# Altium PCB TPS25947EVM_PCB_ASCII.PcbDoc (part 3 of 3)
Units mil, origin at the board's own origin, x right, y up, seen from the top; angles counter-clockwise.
Board outline 6500 x 3000 mil, 4 copper layers (L1-Top Layer, L2-GND1, L3-PWR/SIG, L4-Bottom Layer), stack 63.4 mil thick; 232 components, 92 nets, 448 pads, 577 vias.
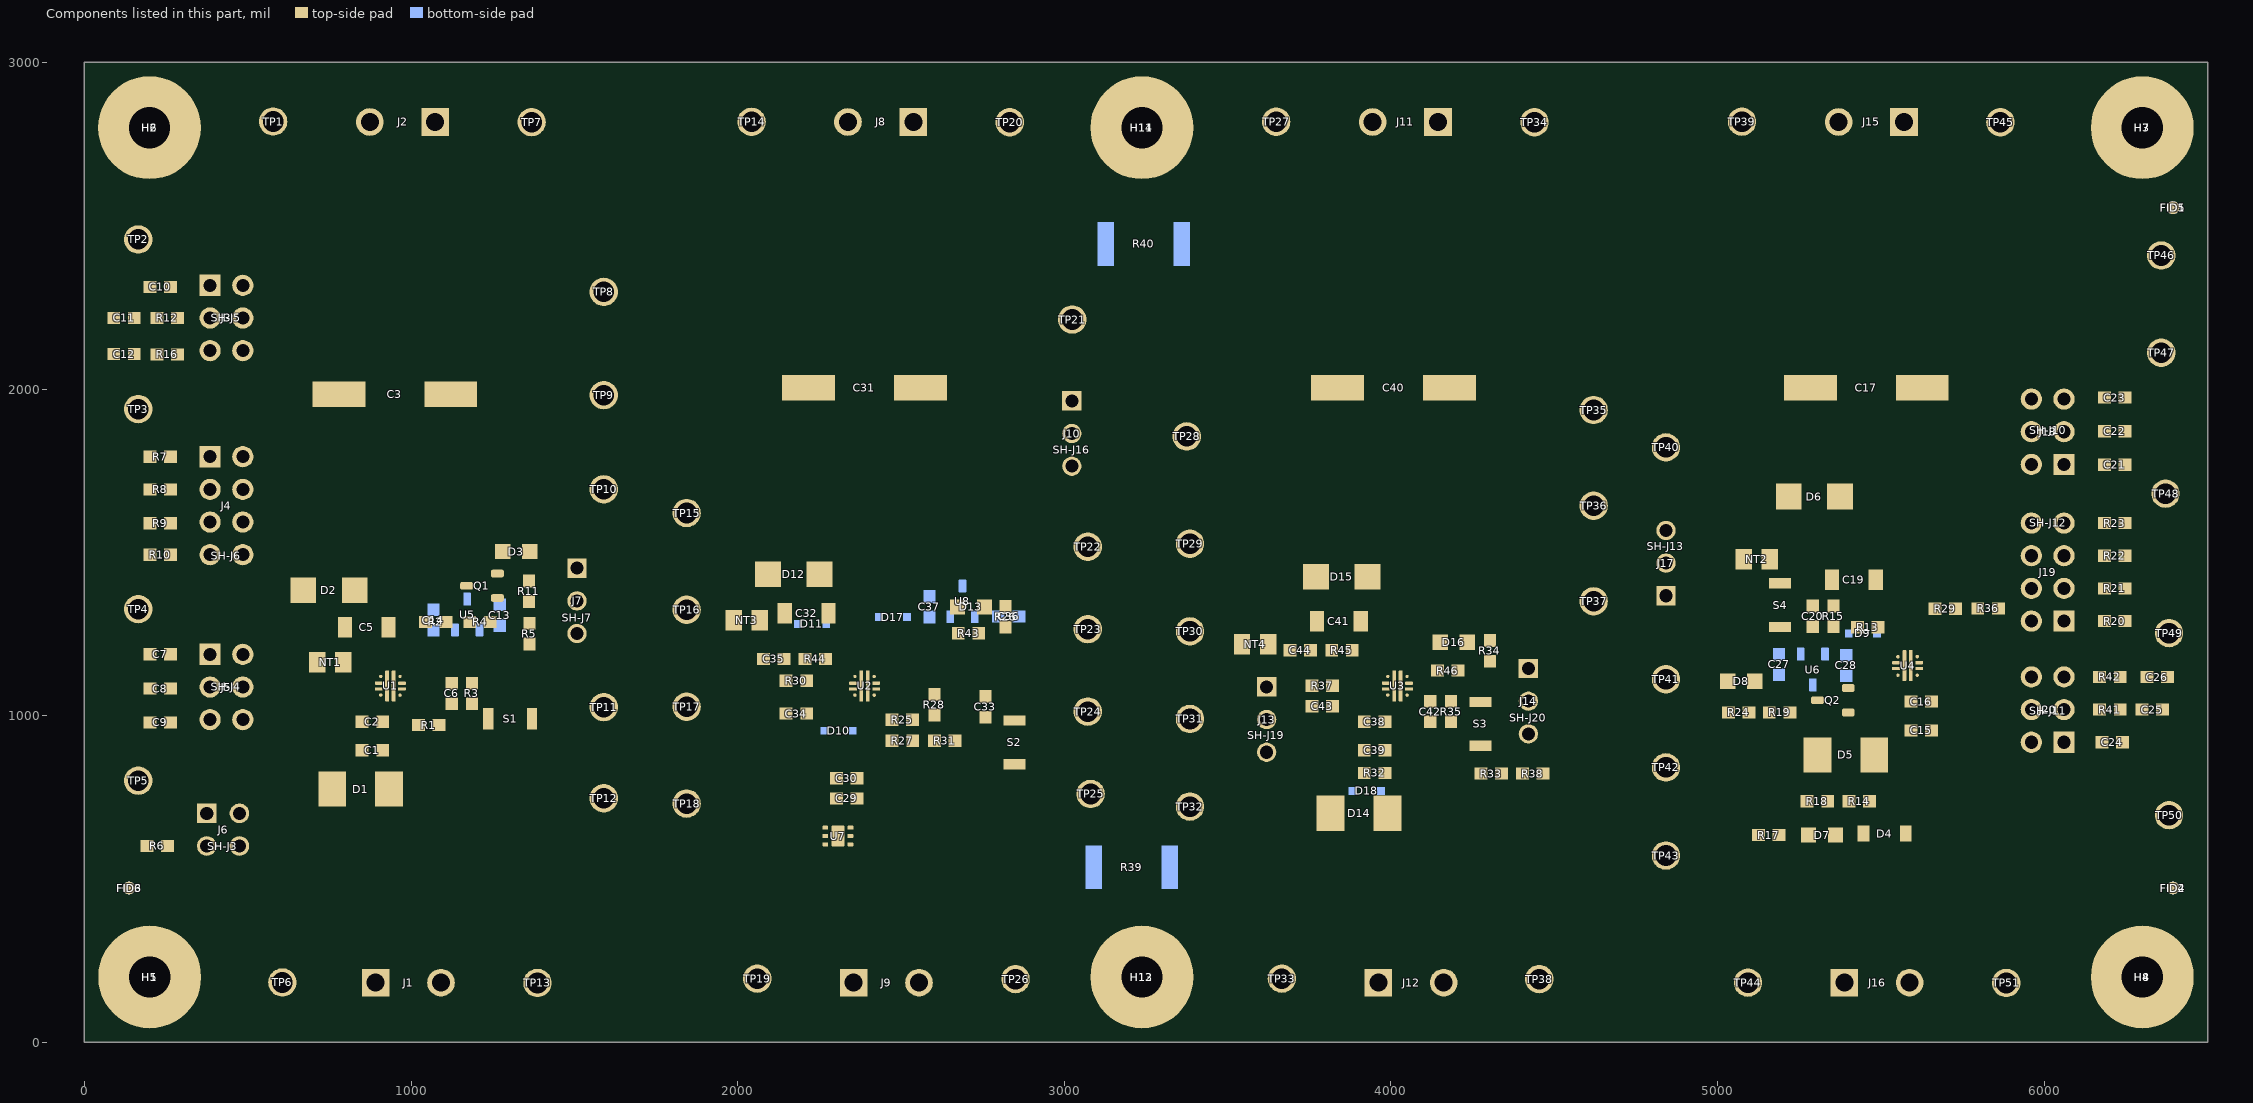
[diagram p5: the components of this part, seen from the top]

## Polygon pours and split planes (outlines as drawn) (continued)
PGND4 on L1-Top Layer "L1-TOP_LAYER_PGND4_P198" (solid, remove dead copper, pour order 198): 5241.83,585.7 5217.29,610.24 5217.29,780.84 5242.85,806.4 5401.8,806.4 5413.77,818.37 5413.77,951.12 5406.54,958.35 5079.85,958.35 5054.9,983.3 5054.9,1309.99 5115.6,1370.69 5115.6,1539.62 5175.32,1599.34 5274.23,1599.34 5292,1617.11 5292,1716.02 5292,1848.56 5456.1,2012.66 5456.1,2872.6 5456.1,2921.2 5419.82,2957.48 4753.68,2957.48 4713.77,2917.57 4713.78,65.62 4739.17,40.23 5440.2,40.23 5477.17,75.84 5477.17,229.99 5477.17,448.39 5477.17,558.13 5449.6,585.7
PGND on L1-Top Layer "L1-TOP_LAYER_PGND_P136" (solid, remove dead copper, pour order 136): 4033.53,262.43 4033.53,277.8 3922.85,388.48 3922.85,727.56 3815.8,834.61 3586.66,834.61 3569.32,851.95 3569.32,1302.32 3636.74,1369.74 3865.56,1369.74 3870.51,1374.69 3870.51,1603.51 3870.51,1853.94 4005.5,1988.93 4005.5,2927.18 3987.68,2945 3290.46,2945 3249.09,2903.63 3249.09,97.1 3306.48,39.7 4004.66,39.7 4033.53,68.56 4033.53,195.15
VIN3 on L1-Top Layer "L1-TOP_LAYER_VIN3_P160" (solid, remove dead copper, pour order 160): 4307.03,797.97 4320.01,784.99 4683.34,784.99 4695.4,772.93 4695.4,287.52 4695.4,64.6 4671.03,40.23 4085.26,40.23 4066.97,58.52 4052.34,73.15 4052.34,282.71 3949.81,385.24 3949.81,804.96 3949.81,1010.2 3961.27,1021.66 4001.85,1021.66 4029.57,1049.38 4076.12,1002.83 4076.12,966.08 4179.54,862.66 4280.71,862.66 4307.03,836.34
VOUT3 on L1-Top Layer "L1-TOP_LAYER_VOUT3_P168" (solid, remove dead copper, pour order 168): 4114,1282.7 4678.65,1282.7 4695.4,1299.46 4695.4,2234.3 4695.4,2915.3 4665.7,2945 4035.36,2945 4020.79,2930.44 4020.79,2736.18 4020.79,1976.24 3885.8,1841.25 3885.8,1258.09 4011.83,1132.06 4108.98,1229.21 4108.98,1277.68
PGND1 on L1-Top Layer "L1-TOP_LAYER_PGND1_P100" (solid, remove dead copper, pour order 100): 978.2,53.6 964.3,39.7 408.7,39.7 380.95,67.45 380.95,470.16 432.76,521.98 520.38,521.98 557.2,558.79 557.2,2416 394.18,2579.02 394.18,2931.41 420.25,2957.48 932.92,2957.48 959.37,2931.03 959.37,1994.84 754.1,1789.57 754.1,870.87 790.61,834.36 855.08,834.36 872.38,817.06 872.38,376.57 978.2,270.74
PGND1 on L1-Top Layer "L1-TOP_LAYER_PGND1_P098" (solid, remove dead copper, pour order 98): 1231.53,1454.75 1225.62,1448.85 1225.62,1393.24 1229.74,1388.22 1315.32,1388.22 1325.75,1398.65 1325.75,1444.66 1315.66,1454.75
VOUT4 on L1-Top Layer "L1-TOP_LAYER_VOUT4_P206" (solid, remove dead copper, pour order 206): 5930.76,2039.26 6452.66,2039.26 6457.48,2044.08 6457.48,2891.89 6391.58,2957.79 6390.29,2956.5 5973.23,2956.5 5503.3,2956.5 5469.69,2922.89 5469.56,1998.48 5311.32,1840.24 5311.32,1588.78 5425.7,1474.4 5425.7,1404.06 5462.67,1367.1 5528.38,1367.1 5585.41,1310.07 5585.41,1193.04 5591.37,1187.07 5597.22,1192.92 5597.22,1198.53 5598.04,1198.53 5614.75,1215.24 5628.65,1215.24 5683.2,1269.8 5683.2,1791.7
VIN4 on L1-Top Layer "L1-TOP_LAYER_VIN4_P200" (solid, remove dead copper, pour order 200): 5495.1,669.31 5430.33,734.08 5430.33,969.73 5566.59,1105.99 5577.11,1105.99 5616.6,1066.5 5616.6,914.4 5843.31,687.69 6084.3,446.7 6084.3,77.38 6046.71,39.78 5535.52,39.78 5495.1,80.2
VIN4 on L1-Top Layer "L1-TOP_LAYER_VIN4_P204" (solid, remove dead copper, pour order 204): 5545.33,1226.29 5494.71,1226.29 5471.21,1249.79 5471.21,1337.1 5481.51,1347.4 5524.5,1347.4 5578.3,1293.6 5578.3,1200.5 5576.33,1198.53 5565.72,1198.53 5565.72,1205.9
EN/UVLO4 on L1-Top Layer "L1-Top Layer-EN/UVLO4" (solid, remove dead copper, pour order 202): 5498,1205.9 5551.06,1205.9 5556.64,1200.33 5556.64,1180.17 5551.94,1175.48 5457.69,1175.48 5457.1,1174.89 5396.56,1235.43 5130.88,1235.43 5123.68,1242.63 5123.68,1282.62 5134.03,1292.97 5444.53,1292.97 5452,1285.5 5452,1251.9
VCC on L1-Top Layer "L1-Top Layer-VCC" (solid, remove dead copper, pour order 124): 4321.73,1186.39 4327.4,1180.72 4327.4,1109.92 4320.01,1102.53 4194.91,1102.53 4183.45,1113.98 4183.45,1175.56 4194.28,1186.39
EN/UVLO3 on L1-Top Layer "L1-TOP_LAYER_EN/UVLO3_P162" (solid, remove dead copper, pour order 162): 4212.28,1024.61 4242.87,994.02 4346.46,994.02 4358.21,1005.77 4358.21,1054.75 4348.36,1064.6 4334.62,1064.6 4139.25,1064.6 4138.63,1063.98 4070.48,1063.98 4065.39,1069.06 4045.32,1069.06 4043.94,1067.69 4043.94,1046.03 4043.35,1045.44 4064.18,1024.61
VIN2 on L1-Top Layer "L1-TOP_LAYER_VIN2_P146" (solid, remove dead copper, pour order 146): 2394.22,1137.83 2394.22,1350.37 2423,1379.15 2515.1,1379.15 2534.16,1360.1 2534.16,1239.58 2447.71,1153.13 2417.43,1153.13 2402.13,1137.83
EN/UVLO2 on L1-Top Layer "L1-TOP_LAYER_EN/UVLO2_P140" (solid, remove dead copper, pour order 140): 2915.72,949.12 2925.03,958.43 2925.03,1011.23 2917.02,1019.23 2809.39,1019.23 2557.96,1019.23 2509.11,1068.08 2422.91,1068.08 2416.88,1062.05 2416.88,1043.34 2428.82,1031.4 2484,1031.4 2513,1002.4 2513,960.76 2524.63,949.12
EN/UVLO1 on L1-Top Layer "L1-TOP_LAYER_EN/UVLO1_P106" (solid, remove dead copper, pour order 106): 984.02,1067.1 970.24,1067.1 966.3,1063.16 966.3,1046.86 988.13,1025.03 1040.59,1025.03 1064.41,1001.2 1064.41,941.2 1068.58,937.03 1266.53,937.03 1282.58,953.08 1282.58,1036.03 1260.15,1058.47 992.64,1058.47
PGND1 on L4-Bottom Layer "L4-BOTTOM_LAYER_PGND1_P126" (solid, remove dead copper, pour order 126): 1580,25.8 1655.7,101.5 1655.7,2912.4 1578.1,2990 82.9,2990 26.8,2933.9 26.8,59.6 60.6,25.8
PGND on L4-Bottom Layer "L4-BOTTOM_LAYER_PGND_P226" (solid, remove dead copper, pour order 226): 4585.87,40.34 4695.4,149.87 4695.4,2885.6 4636,2945 1784.9,2945 1723,2883.1 1724.19,95.21 1779.06,40.34
VIN2 on L4-Bottom Layer "L4-BOTTOM_LAYER_VIN2_P154" (solid, remove dead copper, pour order 154): 3231.29,630.77 3222.86,639.2 2889.76,639.2 2759.52,769.44 2762.72,1034.68 2523.89,1273.51 2523.89,1369.94 2514.68,1379.15 2432.87,1379.15 2402.6,1348.88 2402.6,1045.78 2338.82,982 2338.82,399.9 2462.26,276.47 2462.26,60.02 2490.18,32.1 3090.91,32.1 3135.05,76.24 3135.05,333.15 3231.29,429.39
VOUT2 on L4-Bottom Layer "L4-BOTTOM_LAYER_VOUT2_P196" (solid, remove dead copper, pour order 196): 2960.48,1931.62 2960.48,2014.09 3004.45,2058.06 3139.81,2054.35 3232.6,2147.14 3232.6,2585.55 3212.34,2605.82 3164.54,2605.82 3141.65,2630.38 3141.65,2846.65 3033.76,2954.54 2447.81,2954.54 2439.2,2945.93 2439.2,2102.53 2226.61,1889.94 2226.61,1717.34 2226.61,1279.72 2265.99,1240.35 2295.9,1210.44 2295.9,1050.81 2312.6,1034.11 2361.86,1034.11 2382.7,1054.95 2382.7,1353.85 2425.15,1396.3 2546.45,1396.3 2957.83,1807.68
PGND4 on L4-Bottom Layer "L4-BOTTOM_LAYER_PGND4_P224" (solid, remove dead copper, pour order 224): 4713.4,862.5 4713.4,138.4 4811.2,40.6 6179,40.6 6464.2,325.8 6464.2,2894.4 6377.3,2981.3 4813.97,2981.3 4713.4,2880.73
VIN3 on L4-Bottom Layer "L4-BOTTOM_LAYER_VIN3_P166" (solid, remove dead copper, pour order 166): 4066.97,168.05 4122.26,112.75 4506.17,112.75 4547.4,156.11 4547.4,833.57 4518.32,862.66 4320.9,862.66 4091.58,1091.99 4091.68,1120.37 4074.09,1137.96 4028.95,1137.96 4023.4,1132.42 4023.4,1043.21 3949.81,969.62 3949.81,679.45 3907.03,636.67 3548.93,636.67 3260.84,636.67 3249.05,624.88 3249.05,430.58 3366.52,313.1 4031.44,313.1 4066.97,277.57
VOUT3 on L4-Bottom Layer "L4-BOTTOM_LAYER_VOUT3_P184" (solid, remove dead copper, pour order 184): 4015.9,1168.27 4042.7,1195.07 4290.4,1195.07 4517.26,1421.93 4517.26,1685.96 4517.6,2056.5 4517.6,2859.1 4491.1,2885.6 4048.8,2885.6 4025,2861.8 4025,2740.38 3964.92,2680.3 3346.83,2680.3 3260.84,2594.3 3260.84,2362.67 3284.91,2338.6 3814.08,2338.6 3885.8,2266.87 3885.8,1999.4 3885.8,1073.37 3918.42,1040.76 4001.01,1040.76 4015.9,1055.65
VOUT4 on L4-Bottom Layer "L4-BOTTOM_LAYER_VOUT4_P208" (solid, remove dead copper, pour order 208): 5931.38,2039.88 6453.27,2039.88 6457.48,2044.08 6457.48,2895.65 6393.48,2959.66 5506.46,2959.66 5490.1,2943.3 5490.1,2903.44 5490,2184.78 5311.32,2006.1 5311.32,1588.78 5425.7,1474.4 5425.7,1404.06 5462.67,1367.1 5528.38,1367.1 5585.41,1310.07 5585.41,1193.04 5585.47,1114.8 5594.29,1105.99 5651.69,1105.99 5683.2,1137.5 5683.2,1791.7
NetC28_1 on L4-Bottom Layer "L4-Bottom Layer-NetC28_1" (solid, pour order 212): 5424.95,1178.25 5412.19,1165.49 5314.78,1165.49 5303.34,1176.93 5303.34,1260.62 5309.82,1267.11 5418.51,1267.11 5424.95,1260.67
VIN4 on L4-Bottom Layer "L4-BOTTOM_LAYER_VIN4_P210" (solid, remove dead copper, pour order 210): 5577.11,1296.47 5526.18,1347.4 5481.51,1347.4 5459.4,1325.29 5459.4,998.8 5459.4,317.36 5495.1,281.66 5495.1,132.63 5506.29,121.44 5941.22,121.44 5984.29,164.51 5984.29,546.91 5839.95,691.25 5616.6,914.6 5616.6,1066.5 5577.11,1105.99
GND1 on L2-GND1 "L2-GND1_GND1_P120" (solid, remove dead copper, pour order 120): 1580,25.8 1655.7,101.5 1655.7,2912.4 1578.1,2990 82.9,2990 26.8,2933.9 26.8,59.6 60.6,25.8
GND2 on L2-GND1 "L2-GND1_GND2_P176" (solid, remove dead copper, pour order 176): 1723,96.6 1779,40.6 3167.8,40.6 3216.4,89.2 3216.4,2869.9 3126.64,2959.66 1799.56,2959.66 1723,2883.1 1723,96.4 1744.8,74.6
GND4 on L2-GND1 "L2-GND1_GND4_P180" (solid, remove dead copper, pour order 180): 4713.4,862.5 4713.4,138.4 4811.2,40.6 6179,40.6 6464.2,325.8 6464.2,2894.4 6377.3,2981.3 4863.9,2981.3 4713.4,2830.8
GND3 on L2-GND1 "L2-GND1_GND3_P178" (solid, remove dead copper, pour order 178): 3305.58,40.6 4586.13,40.6 4684.9,139.37 4684.9,2841.9 4581.8,2945 3304.32,2945 3249,2889.68 3249,97.18
PGND1 on L3-PWR/SIG "L3-PWR/SIG_PGND1_P130" (solid, remove dead copper, pour order 130): 1580,25.8 1655.7,101.5 1655.7,2912.4 1578.1,2990 82.9,2990 26.8,2933.9 26.8,59.6 60.6,25.8
PGND on L3-PWR/SIG "L3-PWR/SIG_PGND_P232" (solid, remove dead copper, pour order 232): 1755.4,39.7 4585.23,39.7 4684.9,139.37 4684.9,2841.9 4581.8,2945 1730,2945 1691.45,2906.45 1691.45,103.65
PGND4 on L3-PWR/SIG "L3-PWR/SIG_PGND4_P220" (solid, remove dead copper, pour order 220): 4713.78,862.12 4713.78,138.03 4811.58,40.23 6179.38,40.23 6464.58,325.43 6464.58,2894.02 6377.68,2980.93 4864.28,2980.93 4713.78,2830.43

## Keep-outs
Keep-Out Layer:
  circle w10: c3237.9,2800 r182.44
  circle w10: c3237.9,200.5 r182.44
  circle w10: c200,200 r182.44
  circle w10: c6300,200 r182.44
  circle w10: c6300,2800 r182.44
  circle w10: c200,2800 r182.44
  text ".Layer_Name" at 357.57,-1124.59 h60

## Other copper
L1-Top Layer:
  text ".Layer_Name" at 357.57,-1124.59 h60
L2-GND1:
  text ".Layer_Name" at 356.57,-1126.59 h60
L3-PWR/SIG:
  text ".Layer_Name" at 357.57,-1126.59 h60
L4-Bottom Layer:
  text ".Layer_Name" at 357.57,-1124.59 h60

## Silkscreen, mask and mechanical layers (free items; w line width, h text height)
Top Overlay:
  circle w10: c2240.8,657.2 r2.29
  region: 4441.22,2430.42 4141.22,2430.42 4141.22,2330.42 4441.22,2330.42
  lines w6: 2265.4,1134.47 2265.4,1124.2 2268.6,1121 ; 3919.52,1222.4 3929.92,1232.8 3941.6,1232.8 ; 4247.05,866.89 4248.26,866.89 4266.47,885.1 ; 6241.83,982.37 6241.83,982.32 6256.55,967.6 6275.91,967.6 ; 1984.8,842.08 2711.6,842.08 2711.6,1213.6 2393.78,1213.6 1984.8,1213.6 1984.8,842.08
  lines w8: 1184.03,1905.52 1228.53,1905.52 ; 1206.28,1883.27 1206.28,1927.77 ; 2621.14,1913.8 2665.64,1913.8 ; 2643.39,1891.55 2643.39,1936.05 ; 4239.87,1907.89 4284.37,1907.89 ; 4262.12,1885.64 4262.12,1930.14 ; 5697.5,1905.38 5742,1905.38 ; 5719.75,1883.13 5719.75,1927.63
  lines w10: 1703.2,23.1 1703.2,2989 ; 3238,2410.68 3238,408.84 ; 4708.51,2979.9 4708.6,2630.25 ; 4708.6,2166.2 4708.6,23.25
  text "PGND4" at 5007.4,2657.2 h35
  text "PGND" at 3576.11,2656.22 h35
  text "VOUT3" at 4365.4,2655.2 h35
  text "PGND" at 1979.85,2654.4 h35
  text "VOUT2" at 2765.03,2650.12 h35
  text "VOUT1" at 1319.01,2647.84 h35
  text "VOUT4" at 5795.9,2642.73 h35
  text "PGND1" at 517.43,2641.32 h35
  text "VOUT1" at 909.6,2546.8 h35
  text "VOUT2" at 2361,2544.4 h35
  text "VOUT4" at 5392.6,2542.8 h35
  text "VOUT3" at 4188.17,2540.12 h35
  text "For evaluation only; not" at 2993.37,2500.85 h60
  text "FCC approved for resale." at 2993.37,2439.86 h60
  text "DVDT1" at 254.63,2426.72 h35
  text "DVDT1" at 544.6,2280.2 h35
  text "'.PRJ_Title'" at 4459.34,2268.32 h60
  text "PGTH4" at 6292.8,2248.6 h35
  text "PSIL100" at 4588.02,2203.94 h60
  text "E1" at 5002.41,2203.94 h60
  text "GND1" at 1525.69,2116.73 h35
  text "ITIMER4" at 6055.2,2071.2 h35
  text "VCC_EXT2" at 2898.8,2053.8 h35
  text "ILM1" at 248.23,1905.52 h35
  text "VCC" at 3094.1,1837.08 h35
  text "PGTH1" at 1526.9,1809.15 h35
  text "ILM4" at 6351.6,1804.2 h35
  text "FLTB3" at 4524.2,1769.88 h35
  text "GND3" at 3323.8,1692.4 h35
  text "ILM1" at 553.23,1679.72 h35
  text "EN/UVLO4" at 4789.43,1651.92 h35
  text "PG1" at 1271.2,1549 h35
  text "VCC_EXT1" at 1435.4,1525.6 h35
  text "AUX_OFF3" at 4421.15,1483.66 h35
  text "GND2" at 1787.05,1451.2 h35
  text "FLTB2" at 2603.81,1385.98 h35
  text "DVDT3" at 3310.6,1365.8 h35
  text "FLTB2" at 2955.4,1356.2 h35
  text "DVDT4" at 6448.98,1333.65 h35 r90
  text "TIMER1" at 258.18,1285.42 h35
  text "FLTB3" at 4081.67,1280.02 h35
  text "OVLO3" at 4534,1187 h35
  text "dvdt2" at 1749.78,1159.99 h35
  text "PG4" at 5036.76,1154.91 h35
  text "AUX_OFF2" at 2903.1,1105.4 h35
  text "ILM3" at 3331.22,1096.64 h35
  text "TIMER1" at 544.98,1014.98 h35
  text "VCC_EXT4" at 4725.6,950.8 h35
  text "PG1" at 1558.18,863.61 h35
  text "ILM2" at 1788.6,863.61 h35
  text "EN/UVLO2" at 2947,853 h35
  text "EN/UVLO3" at 3260.4,830 h35
  text "OVCSEL1" at 250.8,775.4 h35
  text "PG4" at 4789.03,675.42 h35
  text "OVLO2" at 2959.8,597.8 h35
  text "ENUVLO1" at 1420.7,579.12 h35
  text "OVCSEL1" at 550.2,563.6 h35
  text "ITIMER3" at 3280.6,558.8 h35
  text "TIMER2" at 1775.25,554.4 h35
  text "GND4" at 6328.93,530.46 h35
  text "RPP" at 5285.98,501.06 h35
  text "OVLO4" at 4772.8,398.59 h35
  text "VIN3" at 4026.43,372.52 h35
  text "VIN2" at 2404.11,372.4 h35
  text "VIN1" at 984.22,371.04 h35
  text "VIN4" at 5438.43,370.12 h35
  text "PGND" at 3600.15,26.5 h35
  text "PGND" at 1997.71,24.82 h35
  text "VIN2" at 2783.63,25.13 h35
  text "VIN3" at 4398.23,23.92 h35
  text "PGND4" at 5005.83,17.52 h35
  text "PGND1" at 539.63,17.32 h35
  text "VIN1" at 1329,17.4 h35
  text "VIN4" at 5827.63,14.12 h35
  text ".Layer_Name" at 357.57,-1124.59 h60
Bottom Overlay:
  circle w10: c1207.65,1223.21 r4.7
  circle w10: c2729,1258.1 r4.7
  circle w10: c5253.2,1229.6 r3.06
  text ".Layer_Name" at 357.57,-1124.59 h60
Top Paste:
  text ".Layer_Name" at 357.57,-1124.59 h60
Bottom Paste:
  text ".Layer_Name" at 357.57,-1124.59 h60
Top Solder:
  text ".Layer_Name" at 357.57,-1124.59 h60
  text ".Layer_Name" at 357.57,-1124.59 h60
Bottom Solder:
  text ".Layer_Name" at 357.57,-1124.59 h60
Drill Guide:
  text ".Layer_Name" at 357.57,-1124.59 h60
M1 Board Outline:
  the board outline again, w10
  text ".Layer_Name" at 357.57,-1124.59 h60
M2 Board Dimensions:
  rectangle: -94.43,-666.09 280.57,-541.09
  rectangle: -219.43,-541.09 -94.43,-416.09
  lines w7: -219.43,-541.09 780.57,-541.09 ; -94.43,-666.09 -94.43,-416.09 ; 30.57,-666.09 30.57,-416.09 ; 280.57,-666.09 280.57,-416.09 ; 530.57,-666.09 530.57,-416.09 ; -219.43,-666.09 -219.43,-416.09 780.57,-416.09 780.57,-666.09 -219.43,-666.09
  text ".Layer_Name" at 357.57,-1124.59 h60
M3 3D STEP Top:
  text ".Layer_Name" at 357.57,-1124.59 h60
M4 3D STEP Bottom:
  text ".Layer_Name" at 357.57,-1124.59 h60
M5 Assembly Top:
  circle w10: c5516.52,1177.85 r3.67
  circle w10: c5420.03,1014.47 r3.67
  circle w10: c4073.4,1064.2 r3.67
  circle w10: c2458.34,1067.83 r3.67
  circle w10: c1280.4,1358.2 r3.67
  circle w10: c1000.98,1064.66 r3.67
  lines w6: 1171.64,2265.02 1209.64,2265.02 ; 1190.64,2246.02 1190.64,2284.01 ; 2605,2260 2643,2260 ; 2624,2241 2624,2279 ; 4228.4,2260.8 4266.4,2260.8 ; 4247.4,2241.8 4247.4,2279.8 ; 5672.4,2257.2 5710.4,2257.2 ; 5691.4,2238.2 5691.4,2276.2
  lines w10: -511.43,-1196.26 6088.57,-1196.26 ; -511.43,-992.93 6090.57,-992.93 ; -511.43,-789.59 -511.43,-1399.59 3493.57,-1399.59 6090.57,-1399.59 6090.57,-789.59 -510.93,-789.59 -510.93,-1399.59 1064.57,-1399.59 ; 1953.57,-1399.59 1953.57,-789.59 ; 3220.57,-992.93 3220.57,-789.59 ; 4060.57,-992.93 4060.57,-789.59 ; 4682.57,-1406.09 4682.57,-1203.26
  text "COMPONENTS MARKED 'DNP' SHOULD NOT BE POPULATED." at 934.07,-584.59 h60
  text "ASSEMBLY VARIANT:" at 933.57,-700.09 h60
  text ".VariantName" at 1969.57,-700.09 h60
  text "PCB VIEWED FROM TOP SIDE" at -447.93,-921.76 h60
  text "BOARD #:" at 2028.57,-921.76 h40
  text "REV:" at 3418.57,-921.76 h60
  text ".PCB_Rev" at 3710.07,-921.76 h60
  text "SVN REV:" at 4256.57,-921.76 h60
  text ".VersionControl_RevNumber" at 4762.57,-921.76 h60
  text ".PRJ_Title" at 2327.5,-924.6 h60
  text ".Layer_Name" at 382.1,-1102.8 h60
  text "TID #:" at 2028.57,-1125.09 h60
  text ".TID" at 2574.07,-1125.09 h60
  text ".plot_File_Name" at 201.5,-1326.7 h50
  text "PLOT NAME =" at -447.93,-1330.43 h60
  text "GENERATED    :" at 2030.57,-1330.43 h60
  text ".Print_Date" at 2900.07,-1330.43 h60
  text ".Print_Time" at 3629.07,-1330.43 h60
  text "TEXAS INSTRUMENTS" at 4893.57,-1330.43 h60
M6 Assembly Bottom:
  circle w10: c1208.65,1242.66 r2.24
  circle w10: c2724.86,1283.07 r2.24
  circle w10: c5253.8,1210.2 r2.24
  lines w10: -511.93,-993.43 6090.07,-993.43 ; -509.93,-1196.76 6090.07,-1196.76 ; 896.07,-1406.59 896.07,-1203.76 ; 1518.07,-993.43 1518.07,-790.09 ; 2358.07,-993.43 2358.07,-790.09 ; 3625.07,-1400.09 3625.07,-790.09 ; 4514.07,-1400.09 6089.57,-1400.09 6089.57,-790.09 -511.93,-790.09 -511.93,-1400.09 2085.07,-1400.09 6090.07,-1400.09 6090.07,-790.09
  text "COMPONENTS MARKED 'DNP' SHOULD NOT BE POPULATED." at 5882.57,-584.09 h60
  text ".VariantName" at 4838.57,-700.09 h60
  text "ASSEMBLY VARIANT:" at 5877.57,-700.09 h60
  text ".PRJ_Title" at 3146.6,-908.8 h60
  text ".VersionControl_RevNumber" at 816.07,-922.26 h60
  text "SVN REV:" at 1322.07,-922.26 h60
  text ".PCB_Rev" at 1868.57,-922.26 h60
  text "REV:" at 2160.07,-922.26 h60
  text "BOARD #:" at 3550.07,-922.26 h40
  text "PCB VIEWED FROM BOTTOM SIDE" at 6026.57,-922.26 h60
  text ".TID" at 3004.57,-1125.59 h60
  text "TID #:" at 3550.07,-1125.59 h60
  text ".Layer_Name" at 5419,-1128 h60
  text ".plot_File_Name" at 5376.1,-1330 h50
  text "TEXAS INSTRUMENTS" at 685.07,-1330.93 h60
  text ".Print_Time" at 1949.57,-1330.93 h60
  text ".Print_Date" at 2678.57,-1330.93 h60
  text "GENERATED    :" at 3548.07,-1330.93 h60
  text "PLOT NAME =" at 6026.57,-1330.93 h60
M7 LPKF Text Top:
  text ".Layer_Name" at 436.7,-1109.9 h60
M8 LPKF Text Bottom:
  text ".Layer_Name" at 399.1,-1097.4 h60
M9 Title Sheet:
  lines w10: -710.93,775.41 -510.93,775.41 ; -710.93,3150.41 -510.93,3150.41 ; -710.93,5525.41 -510.93,5525.41 ; 1789.07,-1599.59 1789.07,-1399.59 ; 1789.07,7700.41 1789.07,7900.41 ; 4289.07,-1599.59 4289.07,-1399.59 ; 4289.07,7700.41 4289.07,7900.41 ; 6101.57,-1399.59 6101.57,-789.59 11084.07,-789.59 ; 6789.07,-1599.59 6789.07,-1399.59 ; 6789.07,7700.41 6789.07,7900.41 ; 9289.07,-1599.59 9289.07,-1399.59 ; 9289.07,7700.41 9289.07,7900.41 ; 11084.07,-1399.59 11084.07,-789.59 ; 11084.07,-1089.59 14084.07,-1089.59 ; 11084.07,-489.59 14084.07,-489.59 ; 11085.07,104.41 14085.07,104.41 ; 11789.07,-1599.59 11789.07,-1399.59 ; 11789.07,7700.41 11789.07,7900.41 ; 12589.07,-1389.59 12589.07,-789.59 ; 14084.07,-789.59 11084.07,-789.59 ; 14084.07,-189.59 11084.07,-189.59 ; 14089.07,-199.59 14089.07,-1399.59 ; 14089.07,604.91 11085.07,604.91 11084.07,604.91 11084.07,104.41 11084.07,-189.59 ; 14089.07,775.41 14289.07,775.41 ; 14089.07,3150.41 14289.07,3150.41 ; 14089.07,5525.41 14289.07,5525.41 ; 11084.07,-789.59 11084.07,-189.59 ; 14089.07,-1399.59 -510.93,-1399.59 -510.93,7700.41 14089.07,7700.41 14089.07,-1399.59 ; -710.93,-1599.59 14289.07,-1599.59 14289.07,7900.41 -710.93,7900.41 -710.93,-1599.59
  text "1" at 520.41,7770.41 h70
  text "2" at 3016.07,7770.41 h70
  text "3" at 5505.42,7770.41 h70
  text "4" at 8012.09,7770.41 h70
  text "5" at 10511.07,7770.41 h70
  text "6" at 13016.07,7770.41 h70
  text "A" at -635.93,6627.41 h70
  text "A" at 14164.07,6627.41 h70
  text "B" at -635.93,4247.41 h70
  text "B" at 14164.07,4247.41 h70
  text "C" at -635.93,1872.41 h70
  text "C" at 14164.07,1872.41 h70
  text "PROJECT TITLE:" at 11124.07,11.41 h45
  text ".PRJ_Title" at 11174.07,-121.92 h70
  text "DESIGNED FOR:" at 11124.07,-289.59 h45
  text ".PRJ_Customer" at 11174.07,-429.59 h70
  text "D" at -635.93,-497.59 h70
  text "D" at 14164.07,-497.59 h70
  text "FILE NAME:" at 11124.07,-589.59 h45
  text ".PCB_File_Name_No_Path" at 11174.07,-709.59 h70
  text "Texas Instruments (TI) and/or its licensors do not warrant the accuracy or completeness of this specification" at 6154.57,-871.43 h45
  text "ENGINEER:" at 11124.07,-879.59 h45
  text "LAYOUT BY:" at 12629.07,-879.59 h45
  text "or any information contained therein. TI and/or its licensors do not warrant that this design will meet" at 6109.59,-984.1 h45
  text ".PRJ_Engineer" at 11174.07,-1034.59 h70
  text ".PCB_Layout" at 12679.57,-1034.59 h70
  text "the specifications, will be suitable for your application or fit for any particular purpose, or will operate in" at 6109.59,-1096.76 h45
  text ".Layer_Name" at 357.57,-1124.59 h60
  text "ALTIUM DESIGNER VERSION:" at 12629.07,-1189.59 h45
  text "an implementation. TI and/or its licensors do not warrant that the design is production worthy. You should" at 6109.59,-1209.43 h45
  text "completely validate and test your design implementation to confirm the system functionality for your application." at 6154.57,-1322.09 h45
  text ".print_Scale" at 11174.07,-1322.92 h70
  text ".Application_BuildNumber" at 12679.57,-1322.92 h70
  text "1" at 520.41,-1529.59 h70
  text "2" at 3016.07,-1529.59 h70
  text "3" at 5505.42,-1529.59 h70
  text "4" at 8012.09,-1529.59 h70
  text "5" at 10511.07,-1529.59 h70
  text "6" at 13016.07,-1529.59 h70
M10 Fab Notes:
  drawing of 189 lines, arcs and shapes, not listed
  text "NOTE:" at 5425.9,6937.2 h60
  text "1.ALL VIAS ARE NON TENTED." at 5667.89,6830.6 h60
  text "2.THIS IS NOT AN IMPEDANCE CONTROLLED BOARD." at 5667.89,6704.6 h60
  text "3. VENDOR MAY ADJUST SOLDERMASK WHEREVER SOLDERMASK PADS ARE THE SAME SIZE (1:1) AS PER THE MANUFACTURING CAPABILITIES" at 5667.89,6575.11 h60
  text "AND ALL OTHER SOLDER MASK PADS SHALL NOT BE MODIFIED, PROVIDED NO ADJACENT COPPER IS EXPOSED AND NO CONFLICT IS PRODUCED" at 5774.62,6476.12 h60
  text "WITH ANY STATED \"VIA TENTING/COVERING\" REQUIREMENTS." at 5774.62,6382.83 h60
  text "DESIGN INFORMATION" at 12162.59,6090.08 h60
  text "MIN. TRACK WIDTH:" at 11518.03,5957.95 h60
  text "9" at 12614.28,5957.96 h60
  text "MIL" at 12769.03,5957.95 h60
  text "MIN. CLEARANCE:" at 11518.03,5833.83 h60
  text "5.118" at 12563.8,5834.2 h60
  text "MIL" at 12845.1,5834.1 h60
  text "MIN. VIA PAD SIZE:" at 11518.03,5709.7 h60
  text "MIL" at 12769.03,5709.7 h60
  text "14" at 12586.3,5706 h60
  text "0.05mm (2MIL)" at 12213.03,5579.8 h60
  text "MINIMUM ANNULAR RING" at 11188.8,5571.58 h60
  text "EXTERNAL" at 12921.03,5571.58 h60
  text "PER" at 11388.8,5461.45 h60
  text "IPC-D-275 CLASS 2 LEVEL C" at 11608.8,5461.45 h60
  text "MIL, HOLES" at 13097.03,5360.97 h60
  text "+/-" at 12704.57,5352.39 h60
  text "+/-" at 13558.57,5352.39 h60
  text "REGISTRATION TOLERANCES:" at 11188.8,5351.32 h60
  text "METAL" at 12388.57,5351.32 h60
  text "5" at 12964.78,5351.33 h60
  text "3" at 13797.78,5351.33 h60
  text "MIL" at 13914.03,5351.32 h60
  text "HOLE SIZE TOLERANCE (UNLESS OTHERWISE SPECIFIED):" at 11188.8,5253.01 h60
  text "+/-" at 13558.57,5250.14 h60
  text "3" at 13797.78,5249.08 h60
  text "MIL" at 13914.03,5249.07 h60
  text "MATERIAL:" at 11114.03,5111.43 h60
  text "FR-4 High Tg" at 12100.48,4982.9 h60
  text "X" at 11956.04,4974.91 h60
  text "FR-408" at 11535.04,4970.39 h60
  text "OTHER" at 13023.03,4970.39 h60
  text "X" at 11735.04,4824.91 h60
  text "62MIL (1.6mm) +/-10%" at 11837,4822 h60
  text "THICKNESS:" at 11188.8,4819.14 h60
  text "OTHER" at 13140.03,4819.14 h60
  text "TOLERANCE:" at 11188.8,4680.83 h60
  text "X" at 12037.04,4680.83 h60
  text "ANSI IPC-6012 TYPE 3 CLASS 2" at 12215.05,4680.83 h60
  text "OTHER +/-" at 12215.03,4536.64 h60
  text "BOW & TWIST:" at 11188.8,4391.45 h60
  text "X" at 12037.04,4391.45 h60
  text "ANSI IPC-6012 TYPE 3 CLASS 2" at 12215.05,4391.45 h60
  text "OTHER +/-" at 12215.03,4244.75 h60
  text "DRILLING:" at 11114.03,4114.14 h60
  text "NC_DRILL FILES" at 12875.03,4008.95 h60
  text "REFERENCE:" at 11188.8,4005.01 h60
  text "X" at 11846.04,4004.91 h60
  text "AS SHOWN" at 12024.03,4005.01 h60
  text "X" at 12747.04,4005.01 h60
  text "OTHER" at 13173.03,3862.76 h60
  text "PTH COPPER THICKNESS:" at 11188.48,3859.23 h60
  text "X" at 12327.72,3859.23 h60
  text "20-30 um" at 12455.71,3859.23 h60
  text "BOARD FINISH:" at 11114.03,3711.63 h60
  text "SILKSCREEN:" at 11269.26,3601.51 h60
  text "X" at 12227.04,3601.51 h60
  text "TOP" at 12344.03,3601.51 h60
  text "BOTTOM" at 12855.03,3601.51 h60
  text "X" at 12734.64,3595.9 h60
  text "SILKSCREEN COLOR:" at 11269.26,3446.32 h60
  text "X" at 12226.04,3446.32 h60
  text "WHITE" at 12344.03,3446.32 h60
  text "OTHER" at 12855.03,3446.32 h60
  text "X" at 12357.04,3302.87 h60
  text "GREEN" at 12475.03,3302.87 h60
  text "OTHER" at 13093.03,3302.87 h60
  text "SOLDER RESIST COLOR:" at 11269.26,3296 h60
  text "X" at 12357.04,3148.62 h60
  text "MATTE" at 12475.03,3148.62 h60
  text "SEMI-GLOSS" at 13092.57,3147.98 h60
  text "IMMERSION GOLD (ENIG)" at 12175.03,2975.84 h60
  text "ENEPIG" at 13512.57,2968.62 h60
  text "SURFACE FINISH:" at 11114.03,2967.62 h60
  text "X" at 11997.04,2967.62 h60
  text "IMM. TIN/SILVER OR EQUIV" at 11443.57,2830.31 h60
  text "OTHER" at 12875.03,2826.37 h60
  text "ARRAY/PANEL:" at 11114.03,2670.99 h60
  text "X" at 11993,2665 h60
  text "CUT AND TRIM PER M1 BOARD OUTLINE" at 12175.03,2662.77 h60
  text "N.C. ROUTE" at 12175.03,2526.8 h60
  text "V. SCORE" at 13041.03,2526.8 h60
  text "CERTIFICATION:" at 11114.03,2397.68 h60
  text "MATERIALS AND WORKMANSHIP FOR ALL PCBS" at 11839.03,2397.68 h60
  text "TO MEET OR EXCEED THE REQUIREMENTS OF:" at 11839.03,2303.61 h60
  text "X" at 11476.54,2174.99 h60
  text "ANSI IPC-A-600F CLASS ->" at 11604.54,2174.99 h60
  text "X" at 13252.54,2174.99 h60
  text "2" at 13362.54,2174.99 h60
  text "1" at 13047.54,2173.49 h60
  text "3" at 13716.54,2173.49 h60
  text "X" at 12288.54,2027.3 h60
  text "RoHS" at 12416.54,2027.3 h60
  text "OTHER" at 13060.94,2027.3 h60
  text "PER ORDER" at 13458,2027.3 h60
  text "ALL BOARDS MUST MEET OR EXCEED UL94-V0 REQUIREMENTS." at 11141.57,1873.47 h60
  text "PCB MUST BEAR THE UL94V-0 UL REGISTERED MATERIAL ID NUMBER" at 11141.57,1757.41 h60
  text "ADDITIONAL REQUIREMENTS:" at 11114.03,1587.99 h60
  text "MICROSECTION:" at 11188.8,1480.86 h60
  text "YES" at 12094.54,1480.86 h60
  text "REQUIRED" at 12956.03,1336.53 h60
  text "BARE BOARD ELEC. TEST:" at 11188.8,1333.67 h60
  text "NONE" at 12494.54,1333.67 h60
  text "X" at 12838.04,1333.67 h60
  text "PER ORDER" at 13548.03,1333.67 h60
  text "XX MIL VIAS REQUIRE NON-CONDUCTIVE FILL AND PLANARIZE" at 11356.95,1128.72 h59
  text "ALL 7.87 AND 12 MIL VIAS REQUIRE TENTING ON BOTH SIDES" at 11364.95,1024.75 h60
  text "OUTER XX MIL TRACES REQUIRE 50 OHM SINGLE-ENDED IMPEDANCE" at 11363.97,861.36 h57
  text "LAYER 2 & 3 (INNER LAYERS) XX MIL WIDE, XX MIL SPACE / TRACES REQUIRE 100 OHM DIFFERENTIAL IMPEDANCE" at 11355.97,625.65 h60
  text ".Layer_Name" at 357.57,-1124.59 h60
M11 Gerber Information:
  lines w10: -511.43,-1196.26 6088.57,-1196.26 ; -511.43,-992.93 6090.57,-992.93 ; -511.43,-789.59 -511.43,-1399.59 3493.57,-1399.59 6090.57,-1399.59 6090.57,-789.59 -510.93,-789.59 -510.93,-1399.59 1064.57,-1399.59 ; 1953.57,-1399.59 1953.57,-789.59 ; 3220.57,-992.93 3220.57,-789.59 ; 4060.57,-992.93 4060.57,-789.59 ; 4682.57,-1406.09 4682.57,-1203.26
  text "ALL ARTWORK VIEWED FROM TOP SIDE" at -447.93,-921.76 h60
  text "BOARD #:" at 2028.57,-921.76 h40
  text "REV:" at 3418.57,-921.76 h60
  text ".PCB_Rev" at 3710.07,-921.76 h60
  text "SVN REV:" at 4256.57,-921.76 h60
  text ".VersionControl_RevNumber" at 4762.57,-921.76 h60
  text ".PRJ_Title" at 2331.9,-924 h60
  text ".Layer_Name" at 291.4,-1112.8 h60
  text "LAYER NAME =" at -447.93,-1124.59 h60
  text "TID #:" at 2028.57,-1125.09 h60
  text ".TID" at 2574.07,-1125.09 h60
  text "PLOT NAME =" at -447.93,-1330.43 h60
  text "GENERATED    :" at 2030.57,-1330.43 h60
  text ".Print_Date" at 2900.07,-1330.43 h60
  text ".Print_Time" at 3629.07,-1330.43 h60
  text "TEXAS INSTRUMENTS" at 4893.57,-1330.43 h60
  text ".plot_File_Name" at 203.9,-1330.7 h50
M12 Stackup:
  drawing of 269 lines, arcs and shapes, not listed
  text "Layer" at 5743.16,5960.8 h60
  text "Name" at 6153.07,5960.8 h60
  text "Material" at 7142.8,5960.8 h60
  text "Thickness" at 8002.56,5960.8 h60
  text "Constant" at 8652.4,5960.8 h60
  text "Board Layer Stack" at 9222.26,5960.8 h60
  text "1" at 5743.16,5840.8 h60
  text "Top Overlay" at 6153.07,5840.8 h60
  text "2" at 5743.16,5720.8 h60
  text "Top Solder" at 6153.07,5720.8 h60
  text "Solder Resist" at 7142.8,5720.8 h60
  text "0.40mil" at 8002.56,5720.8 h60
  text "3.5" at 8652.4,5720.8 h60
  text "3" at 5743.16,5600.8 h60
  text "L1-Top Layer" at 6153.07,5600.8 h60
  text "Copper" at 7142.8,5600.8 h60
  text "2.80mil" at 8002.56,5600.8 h60
  text "4" at 5743.16,5480.8 h60
  text "Dielectric 3" at 6153.07,5480.8 h60
  text "FR-4 HIGH TG" at 7142.8,5480.8 h60
  text "10.00mil" at 8002.56,5480.8 h60
  text "4.2" at 8652.4,5480.8 h60
  text "5" at 5743.16,5360.8 h60
  text "L2-GND1" at 6153.07,5360.8 h60
  text "Copper" at 7142.8,5360.8 h60
  text "1.40mil" at 8002.56,5360.8 h60
  text "6" at 5743.16,5240.8 h60
  text "Dielectric 2" at 6153.07,5240.8 h60
  text "FR-4 HIGH TG" at 7142.8,5240.8 h60
  text "35.00mil" at 8002.56,5240.8 h60
  text "4.2" at 8652.4,5240.8 h60
  text "7" at 5743.16,5120.8 h60
  text "L3-PWR/SIG" at 6153.07,5120.8 h60
  text "Copper" at 7142.8,5120.8 h60
  text "1.40mil" at 8002.56,5120.8 h60
  text "8" at 5743.16,5000.8 h60
  text "Dielectric1" at 6153.07,5000.8 h60
  text "FR-4 HIGH TG" at 7142.8,5000.8 h60
  text "10.00mil" at 8002.56,5000.8 h60
  text "4.2" at 8652.4,5000.8 h60
  text "9" at 5743.16,4880.8 h60
  text "L4-Bottom Layer" at 6153.07,4880.8 h60
  text "Copper" at 7142.8,4880.8 h60
  text "2.80mil" at 8002.56,4880.8 h60
  text "10" at 5743.16,4760.8 h60
  text "Bottom Solder" at 6153.07,4760.8 h60
  text "Solder Resist" at 7142.8,4760.8 h60
  text "0.40mil" at 8002.56,4760.8 h60
  text "3.5" at 8652.4,4760.8 h60
  text ".Layer_Name" at 357.57,-1124.59 h60
M13 Component Bodies Top:
  text ".Layer_Name" at 357.57,-1124.59 h60
M14 Component Bodies Bottom:
  text ".Layer_Name" at 357.57,-1124.59 h60
M15 Courtyards Top:
  text ".Layer_Name" at 357.57,-1124.59 h60
M16 Courtyards Bottom:
  text ".Layer_Name" at 357.57,-1124.59 h60
Drill Drawing:
  circle w10: c5723.62,3981.23 r33.33
  lines w10: 7643.7,2924 8231.7,2924 ; 5690.29,3347.9 5756.96,3347.9 5756.96,3414.57 5690.29,3414.57 5690.29,3347.9 ; 5690.29,3497.9 5723.62,3514.57 5756.96,3497.9 5740.29,3531.23 5756.96,3564.57 5723.62,3547.9 5690.29,3564.57 5706.96,3531.23 5690.29,3497.9 ; 5690.29,3647.9 5690.29,3664.57 5706.96,3681.23 5690.29,3697.9 5690.29,3714.57 5706.96,3714.57 5723.62,3697.9 5740.29,3714.57 5756.96,3714.57 5756.96,3697.9 5740.29,3681.23 5756.96,3664.57 5756.96,3647.9 5740.29,3647.9 5723.62,3664.57 5706.96,3647.9 5690.29,3647.9 ; 5690.29,3814.57 5706.96,3814.57 5723.62,3797.9 5740.29,3814.57 5756.96,3814.57 5740.29,3831.23 5756.96,3847.9 5740.29,3847.9 5723.62,3864.57 5706.96,3847.9 5690.29,3847.9 5706.96,3831.23 5690.29,3814.57 ; 5690.29,4164.57 5756.96,4164.57 5723.62,4097.9 5690.29,4164.57 ; 5690.29,4264.57 5706.96,4264.57 5706.96,4247.9 5740.29,4247.9 5740.29,4264.57 5756.96,4264.57 5756.96,4297.9 5740.29,4297.9 5740.29,4314.57 5706.96,4314.57 5706.96,4297.9 5690.29,4297.9 5690.29,4264.57
  lines w15: 5630.5,3302.9 10921.04,3302.9 ; 5630.5,4352.9 10921.04,4352.9 ; 6181.38,3152.9 6181.38,4502.9 ; 6781.22,3152.9 6781.22,4502.9 ; 7930.88,3152.9 7930.88,4502.9 ; 8436.76,3152.9 8436.76,4502.9 ; 10286.19,3152.9 10286.19,4502.9 ; 5630.5,3152.9 10921.04,3152.9 10921.04,4502.9 5630.5,4502.9 5630.5,3152.9
  text "Symbol" at 5720.5,4397.9 h72
  text "Count" at 6226.38,4397.9 h72
  text "Hole Size" at 6826.22,4397.9 h72
  text "Plated" at 7975.88,4397.9 h72
  text "Drill Layer Pair" at 8481.76,4397.9 h72
  text "Via/Pad" at 10331.19,4397.9 h72
  text "2" at 6226.38,4247.9 h60
  text "7.87mil (0.200mm)" at 6826.22,4247.9 h60
  text "PTH" at 7975.88,4247.9 h60
  text "L1-Top Layer - L4-Bottom Layer" at 8481.76,4247.9 h60
  text "Via" at 10331.19,4247.9 h60
  text "6" at 6226.38,4097.9 h60
  text "125.98mil (3.200mm)" at 6826.22,4097.9 h60
  text "PTH" at 7975.88,4097.9 h60
  text "L1-Top Layer - L4-Bottom Layer" at 8481.76,4097.9 h60
  text "Pad" at 10331.19,4097.9 h60
  text "16" at 6226.38,3947.9 h60
  text "55.12mil (1.400mm)" at 6826.22,3947.9 h60
  text "PTH" at 7975.88,3947.9 h60
  text "L1-Top Layer - L4-Bottom Layer" at 8481.76,3947.9 h60
  text "Pad" at 10331.19,3947.9 h60
  text "24" at 6226.38,3797.9 h60
  text "6.00mil (0.152mm)" at 6826.22,3797.9 h60
  text "PTH" at 7975.88,3797.9 h60
  text "L1-Top Layer - L4-Bottom Layer" at 8481.76,3797.9 h60
  text "Via" at 10331.19,3797.9 h60
  text "51" at 6226.38,3647.9 h60
  text "63.00mil (1.600mm)" at 6826.22,3647.9 h60
  text "PTH" at 7975.88,3647.9 h60
  text "L1-Top Layer - L4-Bottom Layer" at 8481.76,3647.9 h60
  text "Pad" at 10331.19,3647.9 h60
  text "59" at 6226.38,3497.9 h60
  text "40.00mil (1.016mm)" at 6826.22,3497.9 h60
  text "PTH" at 7975.88,3497.9 h60
  text "L1-Top Layer - L4-Bottom Layer" at 8481.76,3497.9 h60
  text "Pad" at 10331.19,3497.9 h60
  text "551" at 6226.38,3347.9 h60
  text "12.00mil (0.305mm)" at 6826.22,3347.9 h60
  text "PTH" at 7975.88,3347.9 h60
  text "L1-Top Layer - L4-Bottom Layer" at 8481.76,3347.9 h60
  text "Via" at 10331.19,3347.9 h60
  text "709 Total" at 6226.38,3197.9 h60
  text "DRILL TOLERANCE" at 7648.7,2942 h40
  text "FOR 6 MIL DRILL +0/- 6 MIL" at 7753.7,2759 h40
  text "FOR 7.87MIL DRILL +0/- 7.87 MIL" at 7753.7,2679.6 h40
  text "FOR 8MIL DRILL +0/- 8 MIL" at 7753.7,2605.4 h40
  text "FOR 12MIL DRILL +0/- 12 MIL" at 7753.7,2531.2 h40
  text "FOR PTH +/-3MILS" at 7753.7,2457 h40
  text ".Layer_Name" at 357.57,-1124.59 h60
M17 Embedded Cavity:
  text ".Layer_Name" at 357.57,-1124.59 h60
M18 Embedded Assembly:
  text ".Layer_Name" at 357.57,-1124.59 h60
M19 Embedded Keepout:
  text ".Layer_Name" at 357.57,-1124.59 h60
